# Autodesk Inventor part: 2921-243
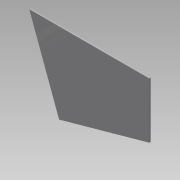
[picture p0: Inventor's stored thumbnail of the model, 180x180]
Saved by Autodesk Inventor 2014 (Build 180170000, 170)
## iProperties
Company: NHTSA/VRTC
Created: 2011-11
Part Number: 2921-243
Material: Steel
Document SubType Name: Modeling
Designer: Mike Vanvoorhis
Density: 7.85 g/cm^3
Project: CHILD SIDE IMPACT SLED
Description: PL 3/8" x 776.7 mm (30.5") x 525.2 mm (20.0")
Mass: 23234.1 g
Surface Area: 6450.81 cm^2
Volume: 2959.75 cm^3
Stock Number: IMPACTOR DOOR PLATE
Appearance: Steel
Author: Dave Walker
Title: IMPACTOR DOOR PLATE
Subject: Child Side Impact Sled
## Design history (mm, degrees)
node "Sketch1"
node "2921-1061"
sketch "Sketch2"
  geometry: L1 (774.7, 0)-(587.325, 506.183) reference; L2 (0, 0)-(774.7, 0); L3 (781.733, -19)-(0, -19); L4 (0, -19)-(0, 0); L5 (774.7, 0)-(781.733, -19); L6 (0, 342.9)-(0, 0) reference
  constraints: 8 end point, 2 collinear, 1 horizontal, 1 parallel, 1 point on line
  dimensions: "d0" = 19 distance between parallel lines of L3 L2
extrude "Extrusion1" join sketch "Sketch2" stored distance "d1" = 10; taper "d2" = 0 deg
node "2921-106"
node "Base1"
